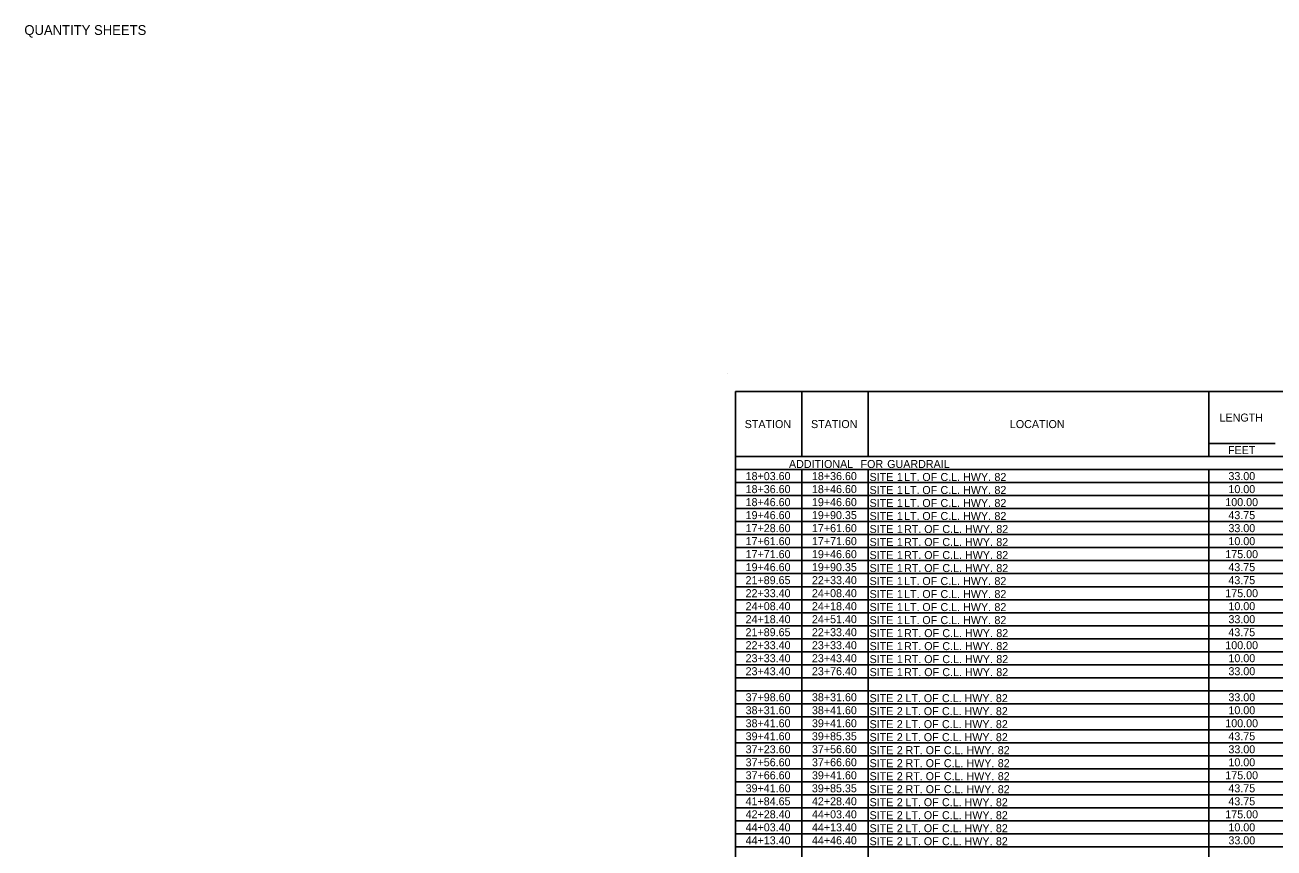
# Model space of a CAD drawing. Extents: x 977434 to 989596, y 1525697 to 1528336.
# Drawn here: x 984085 to 984835, y 1527827 to 1528321 of the extents above; entities that cross this region are included whole.
import ezdxf

# ---------------------------------------------------------------- set-up
doc = ezdxf.new("R2010")
doc.units = 0
doc.layers.add('Default', color=7, linetype='Continuous')
doc.layers.add('R_Border Prem', color=7, linetype='Continuous')

msp = doc.modelspace()

# ---------------------------------------------------------------- linework, layer by layer
at = {"layer": 'Default'}
for p, q in [((984511.57, 1528101.06), (985869.55, 1528101.06)), ((984511.57, 1527640.86), (984511.57, 1528101.06)), ((984511.57, 1527640.86), (984511.57, 1528101.06)), ((984551.35, 1528062.06), (984551.35, 1528101.06)), ((984591.13, 1528062.06), (984591.13, 1528101.06)), ((984795.49, 1528062.06), (984795.49, 1528101.06)), ((984795.49, 1528069.86), (984835.27, 1528069.86)), ((984511.57, 1528062.06), (985869.55, 1528062.06)), ((984511.57, 1528054.26), (985869.55, 1528054.26)), ((984551.35, 1527656.46), (984551.35, 1528054.26)), ((984551.35, 1527656.46), (984551.35, 1528054.26)), ((984591.13, 1527656.46), (984591.13, 1528054.26)), ((984591.13, 1527656.46), (984591.13, 1528054.26)), ((984795.49, 1527656.46), (984795.49, 1528054.26)), ((984795.49, 1527656.46), (984795.49, 1528054.26)), ((984511.57, 1528046.46), (985869.55, 1528046.46)), ((984511.57, 1528038.66), (985869.55, 1528038.66)), ((984511.57, 1528030.86), (985869.55, 1528030.86)), ((984511.57, 1528023.06), (985869.55, 1528023.06)), ((984511.57, 1528015.26), (985869.55, 1528015.26)), ((984511.57, 1528007.46), (985869.55, 1528007.46)), ((984511.57, 1527999.66), (985869.55, 1527999.66)), ((984511.57, 1527991.86), (985869.55, 1527991.86)), ((984511.57, 1527984.06), (985869.55, 1527984.06)), ((984511.57, 1527976.26), (985869.55, 1527976.26)), ((984511.57, 1527968.46), (985869.55, 1527968.46)), ((984511.57, 1527960.66), (985869.55, 1527960.66)), ((984511.57, 1527952.86), (985869.55, 1527952.86)), ((984511.57, 1527945.06), (985869.55, 1527945.06)), ((984511.57, 1527937.26), (985869.55, 1527937.26)), ((984511.57, 1527929.46), (985869.55, 1527929.46)), ((984511.57, 1527921.66), (985869.55, 1527921.66)), ((984511.57, 1527913.86), (985869.55, 1527913.86)), ((984511.57, 1527906.06), (985869.55, 1527906.06)), ((984511.57, 1527898.26), (985869.55, 1527898.26)), ((984511.57, 1527890.46), (985869.55, 1527890.46)), ((984511.57, 1527882.66), (985869.55, 1527882.66)), ((984511.57, 1527874.86), (985869.55, 1527874.86)), ((984511.57, 1527867.06), (985869.55, 1527867.06)), ((984511.57, 1527859.26), (985869.55, 1527859.26)), ((984511.57, 1527851.46), (985869.55, 1527851.46)), ((984511.57, 1527843.66), (985869.55, 1527843.66)), ((984511.57, 1527835.86), (985869.55, 1527835.86)), ((984511.57, 1527828.06), (985869.55, 1527828.06))]:
    msp.add_line(p, q, dxfattribs=at)
at = {"layer": 'R_Border Prem'}
msp.add_line((984506.89, 1528111.98), (984506.89, 1528111.98), dxfattribs=at)

# ---------------------------------------------------------------- texts
at = {"layer": 'Default'}
for s, p in [('LENGTH', (984801.85, 1528083.06)), ('STATION', (984517.01, 1528079.16)), ('STATION', (984556.79, 1528079.16)), ('LOCATION', (984676.07, 1528079.16)), ('FEET', (984806.88, 1528063.56)), ('ADDITIONAL', (984543.55, 1528055.22)), (' FOR', (984584.71, 1528055.22)), (' GUARDRAIL', (984600.7, 1528055.22)), ('18+03.60', (984517.55, 1528047.96)), ('18+36.60', (984557.33, 1528047.96)), ('SITE', (984591.91, 1528047.42)), (' 1', (984606.46, 1528047.42)), (' LT.', (984610.82, 1528047.42)), (' OF', (984621.78, 1528047.42)), (' C.L.', (984632.65, 1528047.42)), (' HWY.', (984646.23, 1528047.42)), (' 82', (984665.01, 1528047.42)), ('33.00', (984807.16, 1528047.96)), ('18+36.60', (984517.55, 1528040.16)), ('18+46.60', (984557.33, 1528040.16)), ('SITE', (984591.91, 1528039.62)), (' 1', (984606.46, 1528039.62)), (' LT.', (984610.82, 1528039.62)), (' OF', (984621.78, 1528039.62)), (' C.L.', (984632.65, 1528039.62)), (' HWY.', (984646.23, 1528039.62)), (' 82', (984665.01, 1528039.62)), ('10.00', (984807.16, 1528040.16)), ('18+46.60', (984517.55, 1528032.36)), ('19+46.60', (984557.33, 1528032.36)), ('SITE', (984591.91, 1528031.82)), (' 1', (984606.46, 1528031.82)), (' LT.', (984610.82, 1528031.82)), (' OF', (984621.78, 1528031.82)), (' C.L.', (984632.65, 1528031.82)), (' HWY.', (984646.23, 1528031.82)), (' 82', (984665.01, 1528031.82)), ('100.00', (984805.29, 1528032.36)), ('19+46.60', (984517.55, 1528024.56)), ('19+90.35', (984557.3, 1528024.56)), ('SITE', (984591.91, 1528024.02)), (' 1', (984606.46, 1528024.02)), (' LT.', (984610.82, 1528024.02)), (' OF', (984621.78, 1528024.02)), (' C.L.', (984632.65, 1528024.02)), (' HWY.', (984646.23, 1528024.02)), (' 82', (984665.01, 1528024.02)), ('43.75', (984807.13, 1528024.56)), ('17+28.60', (984517.55, 1528016.76)), ('17+61.60', (984557.33, 1528016.76)), ('SITE', (984591.91, 1528016.22)), (' 1', (984606.46, 1528016.22)), (' RT.', (984610.82, 1528016.22)), (' OF', (984622.9, 1528016.22)), (' C.L.', (984633.77, 1528016.22)), (' HWY.', (984647.34, 1528016.22)), (' 82', (984666.13, 1528016.22)), ('33.00', (984807.16, 1528016.76)), ('17+61.60', (984517.55, 1528008.96)), ('17+71.60', (984557.33, 1528008.96)), ('SITE', (984591.91, 1528008.42)), (' 1', (984606.46, 1528008.42)), (' RT.', (984610.82, 1528008.42)), (' OF', (984622.9, 1528008.42)), (' C.L.', (984633.77, 1528008.42)), (' HWY.', (984647.34, 1528008.42)), (' 82', (984666.13, 1528008.42)), ('10.00', (984807.16, 1528008.96)), ('17+71.60', (984517.55, 1528001.16)), ('19+46.60', (984557.33, 1528001.16)), ('SITE', (984591.91, 1528000.62)), (' 1', (984606.46, 1528000.62)), (' RT.', (984610.82, 1528000.62)), (' OF', (984622.9, 1528000.62)), (' C.L.', (984633.77, 1528000.62)), (' HWY.', (984647.34, 1528000.62)), (' 82', (984666.13, 1528000.62)), ('175.00', (984805.29, 1528001.16)), ('19+46.60', (984517.55, 1527993.36)), ('19+90.35', (984557.3, 1527993.36)), ('SITE', (984591.91, 1527992.82)), (' 1', (984606.46, 1527992.82)), (' RT.', (984610.82, 1527992.82)), (' OF', (984622.9, 1527992.82)), (' C.L.', (984633.77, 1527992.82)), (' HWY.', (984647.34, 1527992.82)), (' 82', (984666.13, 1527992.82)), ('43.75', (984807.13, 1527993.36)), ('21+89.65', (984517.52, 1527985.56)), ('22+33.40', (984557.33, 1527985.56)), ('SITE', (984591.91, 1527985.02)), (' 1', (984606.46, 1527985.02)), (' LT.', (984610.82, 1527985.02)), (' OF', (984621.78, 1527985.02)), (' C.L.', (984632.65, 1527985.02)), (' HWY.', (984646.23, 1527985.02)), (' 82', (984665.01, 1527985.02)), ('43.75', (984807.13, 1527985.56)), ('22+33.40', (984517.55, 1527977.76)), ('24+08.40', (984557.33, 1527977.76)), ('SITE', (984591.91, 1527977.22)), (' 1', (984606.46, 1527977.22)), (' LT.', (984610.82, 1527977.22)), (' OF', (984621.78, 1527977.22)), (' C.L.', (984632.65, 1527977.22)), (' HWY.', (984646.23, 1527977.22)), (' 82', (984665.01, 1527977.22)), ('175.00', (984805.29, 1527977.76)), ('24+08.40', (984517.55, 1527969.96)), ('24+18.40', (984557.33, 1527969.96)), ('SITE', (984591.91, 1527969.42)), (' 1', (984606.46, 1527969.42)), (' LT.', (984610.82, 1527969.42)), (' OF', (984621.78, 1527969.42)), (' C.L.', (984632.65, 1527969.42)), (' HWY.', (984646.23, 1527969.42)), (' 82', (984665.01, 1527969.42)), ('10.00', (984807.16, 1527969.96)), ('24+18.40', (984517.55, 1527962.16)), ('24+51.40', (984557.33, 1527962.16)), ('SITE', (984591.91, 1527961.62)), (' 1', (984606.46, 1527961.62)), (' LT.', (984610.82, 1527961.62)), (' OF', (984621.78, 1527961.62)), (' C.L.', (984632.65, 1527961.62)), (' HWY.', (984646.23, 1527961.62)), (' 82', (984665.01, 1527961.62)), ('33.00', (984807.16, 1527962.16)), ('21+89.65', (984517.52, 1527954.36)), ('22+33.40', (984557.33, 1527954.36)), ('SITE', (984591.91, 1527953.82)), (' 1', (984606.46, 1527953.82)), (' RT.', (984610.82, 1527953.82)), (' OF', (984622.9, 1527953.82)), (' C.L.', (984633.77, 1527953.82)), (' HWY.', (984647.34, 1527953.82)), (' 82', (984666.13, 1527953.82)), ('43.75', (984807.13, 1527954.36)), ('22+33.40', (984517.55, 1527946.56)), ('23+33.40', (984557.33, 1527946.56)), ('SITE', (984591.91, 1527946.02)), (' 1', (984606.46, 1527946.02)), (' RT.', (984610.82, 1527946.02)), (' OF', (984622.9, 1527946.02)), (' C.L.', (984633.77, 1527946.02)), (' HWY.', (984647.34, 1527946.02)), (' 82', (984666.13, 1527946.02)), ('100.00', (984805.29, 1527946.56)), ('23+33.40', (984517.55, 1527938.76)), ('23+43.40', (984557.33, 1527938.76)), ('SITE', (984591.91, 1527938.22)), (' 1', (984606.46, 1527938.22)), (' RT.', (984610.82, 1527938.22)), (' OF', (984622.9, 1527938.22)), (' C.L.', (984633.77, 1527938.22)), (' HWY.', (984647.34, 1527938.22)), (' 82', (984666.13, 1527938.22)), ('10.00', (984807.16, 1527938.76)), ('23+43.40', (984517.55, 1527930.96)), ('23+76.40', (984557.33, 1527930.96)), ('SITE', (984591.91, 1527930.42)), (' 1', (984606.46, 1527930.42)), (' RT.', (984610.82, 1527930.42)), (' OF', (984622.9, 1527930.42)), (' C.L.', (984633.77, 1527930.42)), (' HWY.', (984647.34, 1527930.42)), (' 82', (984666.13, 1527930.42)), ('33.00', (984807.16, 1527930.96)), ('37+98.60', (984517.55, 1527915.36)), ('38+31.60', (984557.33, 1527915.36)), ('SITE', (984591.91, 1527914.82)), (' 2', (984606.46, 1527914.82)), (' LT.', (984611.7, 1527914.82)), (' OF', (984622.66, 1527914.82)), (' C.L.', (984633.53, 1527914.82)), (' HWY.', (984647.11, 1527914.82)), (' 82', (984665.89, 1527914.82)), ('33.00', (984807.16, 1527915.36)), ('38+31.60', (984517.55, 1527907.56)), ('38+41.60', (984557.33, 1527907.56)), ('10.00', (984807.16, 1527907.56)), ('38+41.60', (984517.55, 1527899.76)), ('39+41.60', (984557.33, 1527899.76)), ('SITE', (984591.91, 1527907.02)), (' 2', (984606.46, 1527907.02)), (' LT.', (984611.7, 1527907.02)), (' OF', (984622.66, 1527907.02)), (' C.L.', (984633.53, 1527907.02)), (' HWY.', (984647.11, 1527907.02)), (' 82', (984665.89, 1527907.02)), ('100.00', (984805.29, 1527899.76)), ('SITE', (984591.91, 1527899.22)), (' 2', (984606.46, 1527899.22)), (' LT.', (984611.7, 1527899.22)), (' OF', (984622.66, 1527899.22)), (' C.L.', (984633.53, 1527899.22)), (' HWY.', (984647.11, 1527899.22)), (' 82', (984665.89, 1527899.22)), ('39+41.60', (984517.55, 1527891.96)), ('39+85.35', (984557.3, 1527891.96)), ('SITE', (984591.91, 1527891.42)), (' 2', (984606.46, 1527891.42)), (' LT.', (984611.7, 1527891.42)), (' OF', (984622.66, 1527891.42)), (' C.L.', (984633.53, 1527891.42)), (' HWY.', (984647.11, 1527891.42)), (' 82', (984665.89, 1527891.42)), ('43.75', (984807.13, 1527891.96)), ('37+23.60', (984517.55, 1527884.16)), ('37+56.60', (984557.33, 1527884.16)), ('SITE', (984591.91, 1527883.62)), (' 2', (984606.46, 1527883.62)), (' RT.', (984611.7, 1527883.62)), (' OF', (984623.78, 1527883.62)), (' C.L.', (984634.65, 1527883.62)), (' HWY.', (984648.22, 1527883.62)), (' 82', (984667.01, 1527883.62)), ('33.00', (984807.16, 1527884.16)), ('37+56.60', (984517.55, 1527876.36)), ('37+66.60', (984557.33, 1527876.36)), ('SITE', (984591.91, 1527875.82)), (' 2', (984606.46, 1527875.82)), (' RT.', (984611.7, 1527875.82)), (' OF', (984623.78, 1527875.82)), (' C.L.', (984634.65, 1527875.82)), (' HWY.', (984648.22, 1527875.82)), (' 82', (984667.01, 1527875.82)), ('10.00', (984807.16, 1527876.36)), ('37+66.60', (984517.55, 1527868.56)), ('39+41.60', (984557.33, 1527868.56)), ('SITE', (984591.91, 1527868.02)), (' 2', (984606.46, 1527868.02)), (' RT.', (984611.7, 1527868.02)), (' OF', (984623.78, 1527868.02)), (' C.L.', (984634.65, 1527868.02)), (' HWY.', (984648.22, 1527868.02)), (' 82', (984667.01, 1527868.02)), ('175.00', (984805.29, 1527868.56)), ('39+41.60', (984517.55, 1527860.76)), ('39+85.35', (984557.3, 1527860.76)), ('SITE', (984591.91, 1527860.22)), (' 2', (984606.46, 1527860.22)), (' RT.', (984611.7, 1527860.22)), (' OF', (984623.78, 1527860.22)), (' C.L.', (984634.65, 1527860.22)), (' HWY.', (984648.22, 1527860.22)), (' 82', (984667.01, 1527860.22)), ('43.75', (984807.13, 1527860.76)), ('41+84.65', (984517.52, 1527852.96)), ('42+28.40', (984557.33, 1527852.96)), ('SITE', (984591.91, 1527852.42)), (' 2', (984606.46, 1527852.42)), (' LT.', (984611.7, 1527852.42)), (' OF', (984622.66, 1527852.42)), (' C.L.', (984633.53, 1527852.42)), (' HWY.', (984647.11, 1527852.42)), (' 82', (984665.89, 1527852.42)), ('43.75', (984807.13, 1527852.96)), ('42+28.40', (984517.55, 1527845.16)), ('44+03.40', (984557.33, 1527845.16)), ('SITE', (984591.91, 1527844.62)), (' 2', (984606.46, 1527844.62)), (' LT.', (984611.7, 1527844.62)), (' OF', (984622.66, 1527844.62)), (' C.L.', (984633.53, 1527844.62)), (' HWY.', (984647.11, 1527844.62)), (' 82', (984665.89, 1527844.62)), ('175.00', (984805.29, 1527845.16)), ('44+03.40', (984517.55, 1527837.36)), ('44+13.40', (984557.33, 1527837.36)), ('SITE', (984591.91, 1527836.82)), (' 2', (984606.46, 1527836.82)), (' LT.', (984611.7, 1527836.82)), (' OF', (984622.66, 1527836.82)), (' C.L.', (984633.53, 1527836.82)), (' HWY.', (984647.11, 1527836.82)), (' 82', (984665.89, 1527836.82)), ('10.00', (984807.16, 1527837.36)), ('44+13.40', (984517.55, 1527829.56)), ('44+46.40', (984557.33, 1527829.56)), ('SITE', (984591.91, 1527829.02)), (' 2', (984606.46, 1527829.02)), (' LT.', (984611.7, 1527829.02)), (' OF', (984622.66, 1527829.02)), (' C.L.', (984633.53, 1527829.02)), (' HWY.', (984647.11, 1527829.02)), (' 82', (984665.89, 1527829.02)), ('33.00', (984807.16, 1527829.56))]:
    msp.add_text(s, height=4.8, dxfattribs=at).set_placement(p)
at = {"layer": 'R_Border Prem'}
msp.add_text('QUANTITY SHEETS', height=5.862, rotation=360, dxfattribs=at).set_placement((984084.91, 1528314.92))

doc.saveas('drawing.dxf')
